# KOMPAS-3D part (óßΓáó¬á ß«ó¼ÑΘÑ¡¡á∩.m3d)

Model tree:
1. Эскиз:1
2. Операция выдавливания:1
     Расстояние 1 = 2
3. Эскиз:2
4. Операция выдавливания:2
     Расстояние 1 = 30
5. Оболочка:1
     Толщина стенки 2 = 2
6. Скругление:4
     Радиус = 1
7. Эскиз:5
8. Операция выдавливания:5
     Расстояние 1 = 10; Расстояние 2 = 27.5
9. Эскиз:6
10. Вырезать элемент выдавливания:1
     Расстояние 1 = 10
11. Эскиз:7
12. Операция выдавливания:6
     Расстояние 1 = 30; Расстояние 2 = 27.5
13. Фаска:2
     Угол = 68; Длина 1 = 12; Длина 2 = 29.701
14. Эскиз:8
15. Операция выдавливания:7
     Расстояние 1 = 7.5; Расстояние 2 = 27.5
16. Скругление:6
     Радиус = 1
17. Скругление:7
     Радиус = 1
18. Скругление:8
     Радиус = 1
19. Скругление:9
     Радиус = 1
20. Скругление:10
     Радиус = 1
21. Скругление:11
     Радиус = 1
22. Скругление:12
     Радиус = 1
23. Скругление:13
     Радиус = 1
24. Эскиз:9
25. Вырезать элемент выдавливания:2
     Расстояние 1 = 2
26. Скругление:14
     Радиус = 1
27. Скругление:15
     Радиус = 1
28. Скругление:16
     Радиус = 1
29. Скругление:17
     Радиус = 1
